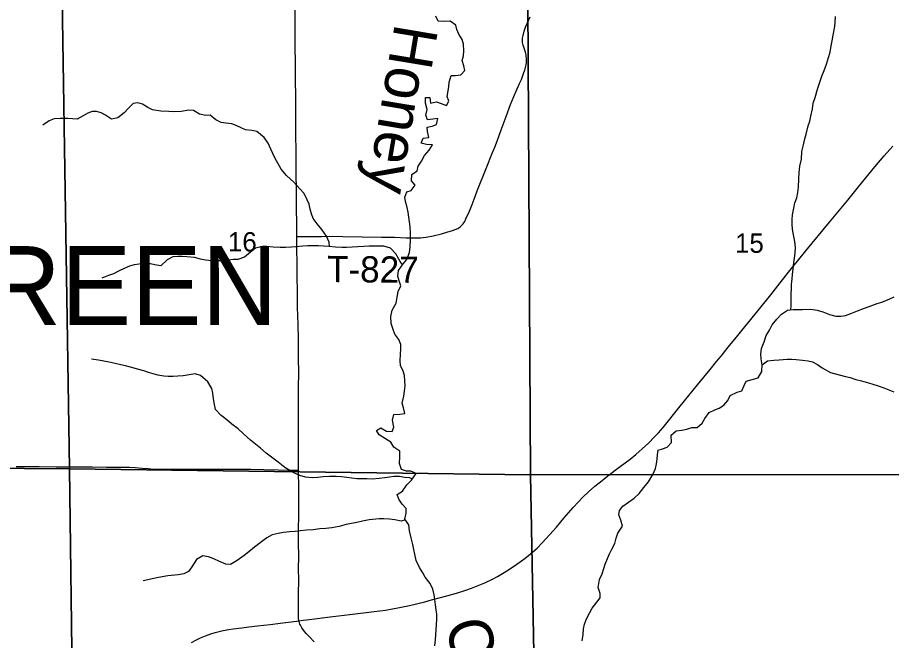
# Model space of a CAD drawing. Extents: x 1874609 to 2204689, y 815661 to 1281160.
# Drawn here: x 2023896 to 2033877, y 975217 to 982336 of the extents above; entities that cross this region are included whole.
import ezdxf

# ---------------------------------------------------------------- set-up
doc = ezdxf.new("R2010")
doc.units = 0
for name, color, linetype in [('GM_X_County_Road', 7, 'Continuous'), ('GM_X_Minor_River', 7, 'Continuous'), ('GM_X_Minor_River_Text', 7, 'Continuous'), ('GM_X_Section', 7, 'Continuous'), ('GM_X_Section_Text', 7, 'Continuous'), ('GM_X_State_Route', 7, 'Continuous'), ('GM_X_Township_Road', 7, 'Continuous'), ('GM_X_Township_Road_Text', 7, 'Continuous'), ('GM_X_Township_Text', 7, 'Continuous')]:
    doc.layers.add(name, color=color, linetype=linetype)

msp = doc.modelspace()

# ---------------------------------------------------------------- linework, layer by layer
at = {"layer": 'GM_X_County_Road'}
for points in [[(2027086.3, 979832.1), (2027084.8, 979944.2), (2027082.4, 980190.1), (2027081.7, 980370.5), (2027079.4, 980551.1), (2027077.5, 980649.4), (2027077.3, 980731.1), (2027076.9, 980845.8), (2027075.2, 980960.6), (2027073.5, 981223), (2027073.6, 981337.7), (2027073.2, 981436.1), (2027069.7, 981616.3), (2027070.1, 981796.5), (2027066.3, 982026.1), (2027065.2, 982239.2), (2027065.4, 982436), (2027068.4, 982501.2), (2027071.7, 982530.1)], [(2027106.7, 977164.9), (2027106.5, 977287.6), (2027105.9, 977451.5), (2027106.6, 977615.4), (2027106, 977795.8), (2027105.4, 977976.1), (2027105.9, 978107.4), (2027107.4, 978271.3), (2027106.6, 978451.9), (2027104, 978665.2), (2027099.8, 978829.2), (2027095, 979025.9), (2027092.4, 979189.9), (2027090.1, 979386.7), (2027088.8, 979501.5), (2027087.1, 979714.5), (2027086.3, 979829.3), (2027086.3, 979832.1)], [(2027110, 975441.8), (2027108.3, 975451.5), (2027106.6, 975467.3), (2027105.3, 975614.6), (2027105.1, 975745.9), (2027106.8, 975909.7), (2027106.5, 976041), (2027106.8, 976172.2), (2027105.8, 976336.2), (2027106, 976467.3), (2027107.8, 976664.2), (2027106.8, 976959.5), (2027106.7, 977156.4), (2027106.7, 977164.9)], [(2027284.2, 975204), (2027227.1, 975262.6), (2027194.2, 975298.8), (2027163.4, 975336.7), (2027144.8, 975363.2), (2027128.5, 975391.1), (2027121.7, 975405.6), (2027115.8, 975420.6), (2027111.2, 975435.8), (2027110, 975441.8)]]:
    msp.add_lwpolyline(points, dxfattribs=at)
at = {"layer": 'GM_X_Minor_River'}
for points in [[(2028973.3, 981844.2), (2028987.4, 981896.3), (2028993.5, 981954.4), (2028987.5, 982030.6), (2028975.6, 982084.8), (2028935.6, 982146.9), (2028911.6, 982197.1), (2028901.6, 982247.2), (2028835.5, 982293.4), (2028769.4, 982291.4), (2028701.2, 982295.4), (2028673.2, 982349.6)], [(2032725.3, 978995.9), (2032725.9, 978991.3), (2032730, 979045.4), (2032732.1, 979099.5), (2032732.2, 979181.7), (2032734.2, 979231.9), (2032736.3, 979284), (2032740.4, 979348.2), (2032746.4, 979398.3), (2032752.5, 979464.4), (2032760.6, 979534.6), (2032768.7, 979584.7), (2032776.8, 979642.9), (2032780.9, 979707), (2032772.9, 979777.2), (2032759, 979853.4), (2032747, 979917.6), (2032743.1, 979975.7), (2032743.2, 980027.8), (2032747.2, 980080), (2032759.4, 980156.2), (2032773.5, 980218.3), (2032793.6, 980276.4), (2032805.7, 980334.6), (2032813.7, 980396.7), (2032817.9, 980491), (2032822, 980563.1), (2032828.1, 980635.3), (2032848.2, 980715.5), (2032854.3, 980805.7), (2032870.4, 980879.9), (2032888.5, 980950.1), (2032900.6, 981002.2), (2032924.8, 981098.4), (2032942.9, 981152.6), (2032957, 981206.7), (2032973.1, 981292.9), (2032983.2, 981357.1), (2033003.3, 981423.2), (2033029.5, 981517.4), (2033055.6, 981585.6), (2033081.8, 981665.8), (2033107.9, 981731.9), (2033134.1, 981802.1), (2033158.2, 981878.3), (2033174.3, 981938.4), (2033188.4, 982010.6), (2033200.5, 982070.7), (2033210.6, 982134.9), (2033228.8, 982231.1), (2033232.8, 982281.3), (2033236.9, 982347.4)], [(2028446.7, 977126.6), (2028386.6, 977150.7), (2028336.5, 977152.8), (2028280.4, 977172.8), (2028258.5, 977241), (2028260.5, 977315.2), (2028262.6, 977379.3), (2028192.5, 977427.5), (2028160.5, 977481.7), (2028098.4, 977521.8), (2028026.3, 977565.9), (2027996.3, 977616.1), (2028046.5, 977648.1), (2028108.6, 977610), (2028174.7, 977603.9), (2028192.8, 977654.1), (2028178.9, 977734.3), (2028195, 977800.4), (2028263.1, 977804.4), (2028317.2, 977812.4), (2028305.3, 977874.6), (2028289.3, 977930.7), (2028307.5, 978008.9), (2028315.5, 978067), (2028321.6, 978127.2), (2028319.7, 978185.3), (2028313.7, 978243.5), (2028301.8, 978293.6), (2028269.8, 978357.8), (2028265.8, 978411.9), (2028269.9, 978490.1), (2028274, 978548.3), (2028272.1, 978600.4), (2028250.1, 978656.5), (2028206.1, 978718.7), (2028184.1, 978770.9), (2028164.1, 978841), (2028160.2, 978919.2), (2028174.3, 978991.4), (2028218.5, 979071.6), (2028230.6, 979139.8), (2028242.7, 979205.9), (2028272.8, 979268.1), (2028252.9, 979326.2), (2028240.9, 979378.3), (2028245, 979446.5), (2028301.2, 979520.7), (2028341.3, 979570.8), (2028373.5, 979651), (2028381.6, 979717.1), (2028383.7, 979795.3), (2028383.8, 979873.5), (2028379.8, 979943.7), (2028371.9, 979999.8), (2028365.9, 980054), (2028356, 980110.1), (2028346, 980164.2), (2028328.1, 980232.4), (2028320.1, 980282.6), (2028340.2, 980342.7), (2028390.4, 980360.7), (2028438.5, 980420.8), (2028394.5, 980471), (2028400.6, 980541.2), (2028458.8, 980585.3), (2028472.8, 980635.4), (2028511, 980693.5), (2028545.1, 980757.7), (2028595.3, 980819.8), (2028635.5, 980881.9), (2028567.3, 980883.9), (2028507.2, 980898), (2028529.3, 980956.2), (2028591.5, 980966.2), (2028577.5, 981034.3), (2028575.6, 981084.4), (2028629.7, 981092.4), (2028679.8, 981112.5), (2028695.9, 981182.6), (2028639.8, 981172.7), (2028577.7, 981166.7), (2028557.7, 981220.8), (2028573.8, 981284.9), (2028555.9, 981355.1), (2028553.9, 981421.3), (2028604, 981421.3), (2028614, 981355.1), (2028682.1, 981371.1), (2028732.2, 981353), (2028796.3, 981329), (2028822.4, 981379.1), (2028802.5, 981431.2), (2028814.6, 981497.4), (2028820.6, 981547.5), (2028824.7, 981597.6), (2028846.8, 981671.8), (2028896.9, 981673.8), (2028959.1, 981681.8), (2029003.2, 981731.9), (2028993.3, 981784), (2028973.3, 981844.2)], [(2027459.6, 979717.1), (2027455.7, 979769.7), (2027423.7, 979835.9), (2027369.7, 979914.1), (2027319.6, 979976.3), (2027273.6, 980038.4), (2027251.6, 980090.6), (2027239.7, 980146.7), (2027225.7, 980202.9), (2027205.7, 980253), (2027167.7, 980323.2), (2027121.7, 980379.4), (2027053.6, 980451.6), (2026967.5, 980529.8), (2026907.5, 980602), (2026869.5, 980670.2), (2026837.5, 980724.4), (2026811.5, 980782.5), (2026789.5, 980832.7), (2026757.5, 980900.8), (2026713.5, 980965), (2026627.4, 981033.2), (2026573.3, 981045.3), (2026501.1, 981053.3), (2026449.1, 981073.4), (2026395, 981103.5), (2026342.9, 981119.6), (2026276.8, 981127.6), (2026222.7, 981137.7), (2026160.6, 981167.8), (2026096.5, 981217.9), (2026046.4, 981214), (2025976.2, 981230), (2025906.1, 981272.2), (2025852, 981276.2), (2025765.8, 981262.2), (2025681.6, 981258.2), (2025625.5, 981262.3), (2025533.3, 981266.3), (2025437.1, 981280.4), (2025385.1, 981308.5), (2025325, 981344.6), (2025270.9, 981360.7), (2025216.8, 981352.7), (2025160.6, 981296.6), (2025112.4, 981246.5), (2025040.2, 981190.4), (2024970, 981172.4), (2024899.9, 981220.5), (2024849.9, 981246.6), (2024797.8, 981262.7), (2024747.7, 981260.7), (2024697.5, 981242.7), (2024647.4, 981210.6), (2024577.2, 981174.5), (2024525.1, 981176.6), (2024471, 981182.6), (2024382.8, 981180.7), (2024316.7, 981178.7), (2024256.5, 981156.7), (2024186.3, 981106.6)], [(2028292.4, 979509.1), (2028267.1, 979546.8), (2028217.1, 979637), (2028155.1, 979699.2), (2028081, 979723.3), (2028020.8, 979721.3), (2027960.7, 979723.3), (2027910.6, 979723.4), (2027850.5, 979719.4), (2027782.3, 979715.4), (2027654, 979707.4), (2027599.9, 979707.5), (2027525.8, 979711.5), (2027453.6, 979717.6), (2027391.5, 979723.6), (2027331.4, 979725.7), (2027277.3, 979727.7), (2027213.1, 979725.7), (2027153, 979721.7), (2027074.8, 979715.7), (2027024.7, 979711.8), (2026956.6, 979707.8), (2026894.4, 979707.8), (2026816.3, 979709.8), (2026744.1, 979717.9), (2026692, 979719.9), (2026613.8, 979699.9), (2026557.7, 979653.8), (2026487.4, 979597.7), (2026411.2, 979571.7), (2026361.1, 979569.7), (2026297, 979561.7), (2026222.8, 979555.7), (2026172.7, 979553.8), (2026114.6, 979553.8), (2026044.5, 979563.8), (2025986.3, 979575.9), (2025918.2, 979594), (2025830, 979602), (2025777.9, 979604.1), (2025727.8, 979604.1), (2025671.7, 979600.1), (2025605.5, 979566.1), (2025531.3, 979499.9), (2025463.2, 979508), (2025413.1, 979520), (2025338.9, 979522.1), (2025286.8, 979518.1), (2025228.7, 979510.1), (2025176.5, 979494.1), (2025112.4, 979466), (2025058.2, 979442), (2024992.1, 979407.9), (2024935.9, 979387.9), (2024859.7, 979355.9)], [(2032398.5, 978367.8), (2032388.6, 978434), (2032384.6, 978490.2), (2032392.7, 978552.3), (2032422.9, 978630.5), (2032447, 978700.7), (2032483.1, 978764.8), (2032515.3, 978824.9), (2032565.5, 978889.1), (2032621.7, 978945.2), (2032687.8, 978991.3), (2032752, 978999.3), (2032802.1, 979001.2), (2032860.2, 979001.2), (2032954.4, 979003.2), (2033026.6, 978993.1), (2033090.7, 978973), (2033166.8, 978940.9), (2033240.9, 978924.8), (2033299.1, 978922.8), (2033351.2, 978930.8), (2033413.3, 978952.8), (2033487.5, 978982.9), (2033567.7, 979012.9), (2033621.9, 979032.9), (2033714.1, 979067), (2033764.2, 979085), (2033856.5, 979123), (2033906.6, 979143.1)], [(2028404.5, 977065.1), (2028370.5, 977074.5), (2028314.4, 977080.6), (2028256.3, 977090.6), (2028194.2, 977090.7), (2028144, 977084.7), (2028089.9, 977076.7), (2028025.8, 977066.7), (2027945.6, 977062.7), (2027883.5, 977064.8), (2027827.3, 977062.8), (2027771.2, 977064.8), (2027713.1, 977070.8), (2027657, 977080.9), (2027594.9, 977088.9), (2027536.8, 977091), (2027460.6, 977091), (2027388.4, 977087), (2027326.3, 977081.1), (2027262.2, 977075.1), (2027184, 977085.1), (2027119.9, 977101.2), (2027049.8, 977131.3), (2026997.7, 977163.4), (2026947.6, 977195.5), (2026871.5, 977253.7), (2026811.5, 977299.8), (2026737.4, 977358), (2026669.3, 977414.2), (2026613.2, 977460.3), (2026557.2, 977506.5), (2026477.1, 977578.7), (2026415, 977634.9), (2026344.9, 977689), (2026284.9, 977737.2), (2026222.8, 977787.3), (2026156.7, 977857.5), (2026144.8, 977915.7), (2026132.8, 977979.9), (2026124.9, 978044), (2026116.9, 978098.2), (2026068.9, 978174.4), (2025984.8, 978246.6), (2025926.7, 978262.7), (2025856.6, 978254.7), (2025786.4, 978242.7), (2025728.3, 978238.7), (2025674.1, 978234.7), (2025618, 978234.7), (2025567.9, 978238.8), (2025497.8, 978250.8), (2025443.7, 978264.9), (2025393.6, 978281), (2025339.5, 978299), (2025267.4, 978317.1), (2025201.3, 978337.2), (2025129.1, 978355.3), (2025075, 978367.3), (2025012.9, 978383.4), (2024942.8, 978399.5), (2024882.7, 978409.5), (2024820.6, 978419.6), (2024740.4, 978433.7)], [(2032398.5, 978367.8), (2032460.7, 978411.9), (2032532.9, 978419.9), (2032593, 978425.9), (2032683.2, 978431.9), (2032733.3, 978431.9), (2032787.4, 978427.8), (2032859.5, 978421.8), (2032923.7, 978413.7), (2032975.8, 978399.7), (2033031.8, 978369.6), (2033083.9, 978331.4), (2033180.1, 978281.3), (2033280.2, 978251.2), (2033350.4, 978235.1), (2033402.5, 978221), (2033470.6, 978200.9), (2033532.7, 978184.9), (2033612.8, 978162.8), (2033662.9, 978146.7), (2033725, 978126.6), (2033787.1, 978102.5), (2033847.2, 978082.5), (2033903.3, 978060.4)], [(2030344.5, 975213), (2030356.6, 975285.2), (2030360.7, 975349.3), (2030370.8, 975403.4), (2030394.9, 975465.6), (2030433.1, 975535.7), (2030457.2, 975585.8), (2030511.4, 975654), (2030549.5, 975704.1), (2030549.6, 975754.2), (2030525.6, 975824.4), (2030543.7, 975914.6), (2030573.9, 975980.8), (2030592, 976038.9), (2030606.1, 976091), (2030632.2, 976155.2), (2030656.3, 976207.3), (2030684.4, 976261.4), (2030718.6, 976327.6), (2030730.7, 976387.7), (2030752.8, 976443.8), (2030803, 976522), (2030785, 976594.2), (2030763.1, 976652.4), (2030769.1, 976702.5), (2030807.3, 976752.6), (2030937.7, 976842.8), (2030993.8, 976896.9), (2031050, 976965), (2031100.2, 977029.1), (2031152.4, 977113.3), (2031182.6, 977181.5), (2031194.7, 977235.6), (2031198.7, 977287.7), (2031202.8, 977339.9), (2031210.9, 977392), (2031263, 977408), (2031315.1, 977428), (2031363.3, 977478.1), (2031359.4, 977562.3), (2031415.6, 977614.4), (2031483.7, 977620.4), (2031537.8, 977630.4), (2031598, 977652.4), (2031656.1, 977650.4), (2031714.3, 977700.5), (2031746.4, 977752.6), (2031792.6, 977822.8), (2031858.8, 977854.8), (2031908.9, 977872.8), (2031961, 977904.9), (2032007.2, 977959), (2032035.3, 978015.2), (2032115.5, 978055.2), (2032167.7, 978071.2), (2032193.8, 978129.4), (2032217.9, 978181.5), (2032284.1, 978199.5), (2032352.2, 978219.5), (2032394.4, 978289.7), (2032398.5, 978367.8)], [(2028660.9, 975157.6), (2028669, 975225.8), (2028673.1, 975283.9), (2028677.2, 975340.1), (2028681.2, 975398.2), (2028683.3, 975462.4), (2028683.4, 975516.5), (2028675.4, 975568.7), (2028667.5, 975624.8), (2028661.5, 975686.9), (2028655.6, 975739.1), (2028639.6, 975805.2), (2028607.6, 975869.4), (2028551.6, 975941.6), (2028525.6, 975991.8), (2028487.6, 976049.9), (2028449.6, 976130.2), (2028431.6, 976204.3), (2028421.7, 976256.5), (2028411.7, 976312.6), (2028391.8, 976388.8), (2028371.8, 976471), (2028365.9, 976539.2), (2028319.9, 976603.4), (2028336, 976671.6), (2028336, 976725.7), (2028288, 976775.8), (2028252, 976832), (2028230, 976886.1), (2028292.2, 976924.2), (2028340.4, 976996.4), (2028394.5, 977050.5), (2028446.7, 977126.6)], [(2028326.3, 976594.4), (2028277.7, 976579.4), (2028205.6, 976595.4), (2028145.5, 976605.5), (2028077.4, 976609.5), (2028025.2, 976607.5), (2027913, 976595.6), (2027836.8, 976581.6), (2027772.7, 976567.6), (2027710.5, 976555.6), (2027648.4, 976541.6), (2027568.2, 976521.5), (2027484, 976503.5), (2027415.8, 976495.6), (2027349.7, 976491.6), (2027271.5, 976483.6), (2027197.3, 976477.6), (2027125.2, 976469.6), (2027065, 976463.6), (2027000.9, 976459.7), (2026932.8, 976451.7), (2026872.6, 976439.7), (2026804.4, 976423.7), (2026744.3, 976389.6), (2026666.1, 976331.5), (2026603.9, 976283.4), (2026537.7, 976231.3), (2026483.5, 976187.2), (2026405.3, 976131.1), (2026327.1, 976085), (2026274.9, 976091.1), (2026202.8, 976119.2), (2026136.7, 976149.3), (2026078.6, 976173.4), (2026012.5, 976183.4), (2025938.3, 976143.4), (2025886.1, 976059.2), (2025847.9, 976005.1), (2025793.8, 975979), (2025731.7, 975969), (2025611.4, 975957.1), (2025507.2, 975937.1), (2025435, 975921.1), (2025382.9, 975909.1), (2025330.7, 975901.1)]]:
    msp.add_lwpolyline(points, dxfattribs=at)
at = {"layer": 'GM_X_Section'}
for points in [[(2019042.1, 982641.5), (2024404.7, 982560.8), (2024490, 977180.5), (2021408.6, 977202.1), (2019175.3, 977309.4)], [(2024404.7, 982560.8), (2029723.2, 982509.9), (2029754.5, 977109.5), (2024490, 977180.5)], [(2029723.2, 982509.9), (2035039.6, 982545), (2035070.9, 977114.6), (2029754.5, 977109.5)], [(2024490, 977180.5), (2024559.1, 971862.4), (2019252.8, 971849.2), (2019175.3, 977309.4), (2021408.6, 977202.1)], [(2029754.5, 977109.5), (2029851.5, 971817.4), (2024559.1, 971862.4), (2024490, 977180.5)], [(2035070.9, 977114.6), (2035115.9, 971820.4), (2029851.5, 971817.4), (2029754.5, 977109.5)]]:
    msp.add_lwpolyline(points, close=True, dxfattribs=at)
at = {"layer": 'GM_X_State_Route'}
msp.add_lwpolyline([(2025883.9, 975193.8), (2025940.6, 975225.2), (2025984.2, 975246.5), (2026044, 975271.9), (2026105, 975294.8), (2026151.6, 975309.6), (2026198.8, 975322.2), (2026246.5, 975332.8), (2026310.7, 975344.8), (2026359.3, 975351.7), (2026456.9, 975363.1), (2026537.9, 975373.2), (2026635, 975385.3), (2026781.1, 975402.1), (2026927.6, 975418.9), (2027024.9, 975432.4), (2027110, 975441.8), (2027156.3, 975449), (2027195.6, 975454.4), (2027495.3, 975491.8), (2027690.9, 975514.7), (2027967.8, 975547.7), (2028097.8, 975564.8), (2028178.5, 975578.2), (2028258.9, 975593.8), (2028370.9, 975618.3), (2028546.1, 975660.5), (2028625.4, 975680.7), (2028799.7, 975727.4), (2028910.2, 975758.1), (2029004, 975787.4), (2029081.1, 975814.5), (2029157.2, 975844.5), (2029232.1, 975877.2), (2029320.7, 975919.3), (2029378.5, 975949.7), (2029435, 975982.4), (2029504, 976026.2), (2029599, 976090.4), (2029678.7, 976147.5), (2029730.5, 976187.4), (2029780.6, 976229.3), (2029828.7, 976273.5), (2029886.2, 976331.6), (2029974.7, 976428.3), (2030050.7, 976514.2), (2030136.1, 976613.8), (2030242.4, 976738.8), (2030297.8, 976799.4), (2030355.3, 976858.1), (2030414.9, 976914.6), (2030489, 976979.6), (2030552.5, 977031.7), (2030617.3, 977082), (2030721.2, 977162.2), (2030891.5, 977290.4), (2030955.1, 977341.9), (2031029, 977406.4), (2031100.8, 977473.5), (2031170.4, 977542.8), (2031214.9, 977590.7), (2031267.7, 977653), (2031463.3, 977895.6), (2031660.4, 978137.1), (2031806, 978314.8), (2031878.5, 978403.7), (2031930.2, 978467.1), (2032012.5, 978568.6), (2032063.9, 978632.5), (2032105.2, 978683.5), (2032167.5, 978759.7), (2032271.4, 978886.5), (2032384.4, 979027.1), (2032497.2, 979168), (2032578.8, 979270.7), (2032701.6, 979424.6), (2032804, 979552.8), (2032896.5, 979668), (2033167.6, 979997), (2033376.1, 980249.7), (2033499.6, 980402.4), (2033582.1, 980503.9), (2033687.3, 980629.2), (2033794.4, 980753.2), (2033891.9, 980864)], dxfattribs=at)
at = {"layer": 'GM_X_Township_Road'}
for points in [[(2028364, 979819), (2028447.2, 979817.6), (2028496.3, 979818), (2028529, 979820.5), (2028561.3, 979825.4), (2028641.3, 979842.5), (2028736.6, 979865), (2028799.7, 979881.4), (2028862.3, 979900.2), (2028892.9, 979911.6), (2028922.5, 979925.6), (2028924.3, 979926.6), (2028936.5, 979933.9), (2028949.8, 979943.4), (2028962.3, 979954), (2028973.7, 979965.6), (2028984.2, 979978.2), (2028993.7, 979991.4), (2029002.4, 980005.4), (2029017.5, 980034.4), (2029056.6, 980124.5), (2029087.3, 980200.5), (2029122.6, 980292.3), (2029145.3, 980353.8), (2029247.5, 980611.4), (2029319.5, 980795), (2029344.9, 980854.7), (2029376.7, 980935.4), (2029419.1, 981050.3), (2029474.8, 981204.3), (2029526.8, 981342.1), (2029563.2, 981433.2), (2029589.1, 981493), (2029630.1, 981581.4), (2029650.1, 981625.9), (2029667.6, 981672), (2029679.8, 981707), (2029688.9, 981734.3), (2029697.6, 981764.9), (2029703, 981793.4), (2029707.5, 981822.3), (2029707.9, 981850), (2029707.5, 981871.9), (2029706.1, 981891.9), (2029704, 981908.1), (2029696.3, 981939.9), (2029671.2, 982017.8), (2029667.1, 982033.6), (2029664.1, 982049.7), (2029662.5, 982065.9), (2029662.4, 982082.3), (2029663.8, 982098.5), (2029669.9, 982130.6), (2029682.9, 982177.7), (2029698.5, 982223.9), (2029717.3, 982268.9), (2029750.5, 982342.2)], [(2027086.3, 979832.1), (2027108.2, 979832.3), (2027169.3, 979832.8), (2027234.8, 979833.7), (2027365.8, 979834.1), (2027496.9, 979835.8), (2027611.6, 979835.2), (2028054, 979826.8), (2028201.5, 979824), (2028332.5, 979819.5), (2028364, 979819)], [(2023880.7, 977207.3), (2024142.5, 977204.1), (2024338.9, 977202.4), (2024469.8, 977203.2), (2024551.7, 977203.4), (2024748.4, 977202.2), (2024912.3, 977198.7), (2024977.8, 977197.3), (2025092.4, 977199), (2025174.4, 977198), (2025239.9, 977194.8), (2025321.6, 977188.4), (2025386.8, 977182.4), (2025451.9, 977176.8), (2025500.7, 977174.8), (2025565.7, 977174.2), (2025743.7, 977174.5), (2025824.6, 977175.8), (2025922.5, 977176.8), (2026168, 977176.1), (2026380.4, 977174.5), (2026560.3, 977173.8), (2026707.6, 977172.6), (2026871.2, 977168.4), (2026985.7, 977164.6), (2027045.4, 977165), (2027105.7, 977164.9), (2027106.7, 977164.9)]]:
    msp.add_lwpolyline(points, dxfattribs=at)

# ---------------------------------------------------------------- texts
at = {"layer": 'GM_X_Minor_River_Text'}
for s, height, rotation, p in [('Honey', 500.13, 260.469, (2028206.5, 982278.3)), ('Creek', 500.12, 283.95131, (2028775.9, 975410.3))]:
    msp.add_text(s, height=height, rotation=rotation, dxfattribs=at).set_placement(p)
at = {"layer": 'GM_X_Section_Text'}
for s, p in [('16', (2026299.1, 979662.2)), ('15', (2032089.5, 979647.3))]:
    msp.add_text(s, height=221, rotation=0.00001, dxfattribs=at).set_placement(p)
at = {"layer": 'GM_X_Township_Road_Text'}
msp.add_text('T-827', height=300, rotation=359.45296, dxfattribs=at).set_placement((2027428.5, 979312.8))
at = {"layer": 'GM_X_Township_Text'}
msp.add_text('GREEN', height=900, rotation=0.00001, dxfattribs=at).set_placement((2022587.4, 978823.5))

doc.saveas('drawing.dxf')
